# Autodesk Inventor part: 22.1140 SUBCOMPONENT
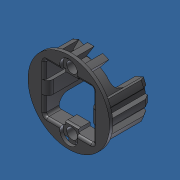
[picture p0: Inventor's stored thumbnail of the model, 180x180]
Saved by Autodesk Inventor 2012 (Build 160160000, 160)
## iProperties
Created: 2014-04
Part Number: 22.1140 SUBCOMPONENT
Material: ABS Plastic
Document SubType Name: Modeling
Designer: Admin
Density: 1.06 g/cm^3
Mass: 11.4279 g
Surface Area: 84.1907 cm^2
Volume: 10.781 cm^3
Description: MULTI CONNECTOR 30 INSERT SUBCOMPONENT
Stock Number: 22.1140 MULTI CONNECTOR 30 INSERT SUBCOMPONENT
Translation Standard: STEP AP214IS
FileName: 22_1140_0_1.stp
PreProcessor: ACIS
PostProcessor: Build: 160, Release: 2012 RTM - Date: Tue 03/01/2011
Sent Units: inch
Uncertainty: 0.0
Author: Admin
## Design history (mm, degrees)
node "61"
sketch "Sketch1"
  geometry: L1 (-7.178, 2)-(-5.905, 2) reference; L2 (-2.5, 4)-(32.5, 4); C1 r 3.3 at (15, 21.5) reference; C2 r 3.3 at (15, -13.5) reference; C3 r 2.5 at (-2.5, 4); C4 r 2.5 at (32.5, 4); A1 r 21 centre (15, 4) between (-5.486, 8.619) and (-5.905, 6) reference; A2 r 22.268 centre (15, 4) between (-6.255, -2.639) and (-4.725, -6.335) reference; A3 r 17.5 centre (15, 4) between (15, 21.5) and (-2.5, 4); 1 further point
  constraints: 3 centre point, 3 coincident, 3 point on circle, 2 end point, 1 equal radius, 1 midpoint, 1 parallel
  dimensions: "d0" = 5 diameter of C4
extrude "Extrusion1" cut sketch "Sketch1" distance "d1" = 21.75; taper "d2" = 0 deg
node "Base1"
body "Solid1"
